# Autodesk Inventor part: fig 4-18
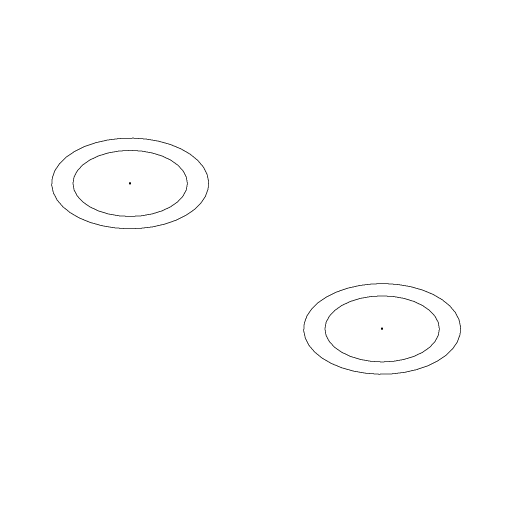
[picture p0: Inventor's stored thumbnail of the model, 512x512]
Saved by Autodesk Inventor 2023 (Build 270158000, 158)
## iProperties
Created: 2005-02
Part Number: fig 4-18
Document SubType Name: Modeling
Designer: CADCIM
Manufacturer: Standard
Standards Organization: Custom
Density: 1 g/cm^3
Material: Generic
Appearance: Default
Author: CADCIM
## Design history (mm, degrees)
sketch "Sketch1"
  geometry: C1 r 7.935 at (-23.563, 7.599); C2 r 7.935 at (12.452, 7.599); C3 r 5.782 at (-23.563, 7.599); C4 r 5.782 at (12.452, 7.599)
  constraints: 4 centre point, 1 coincident, 1 equal radius, 1 other
